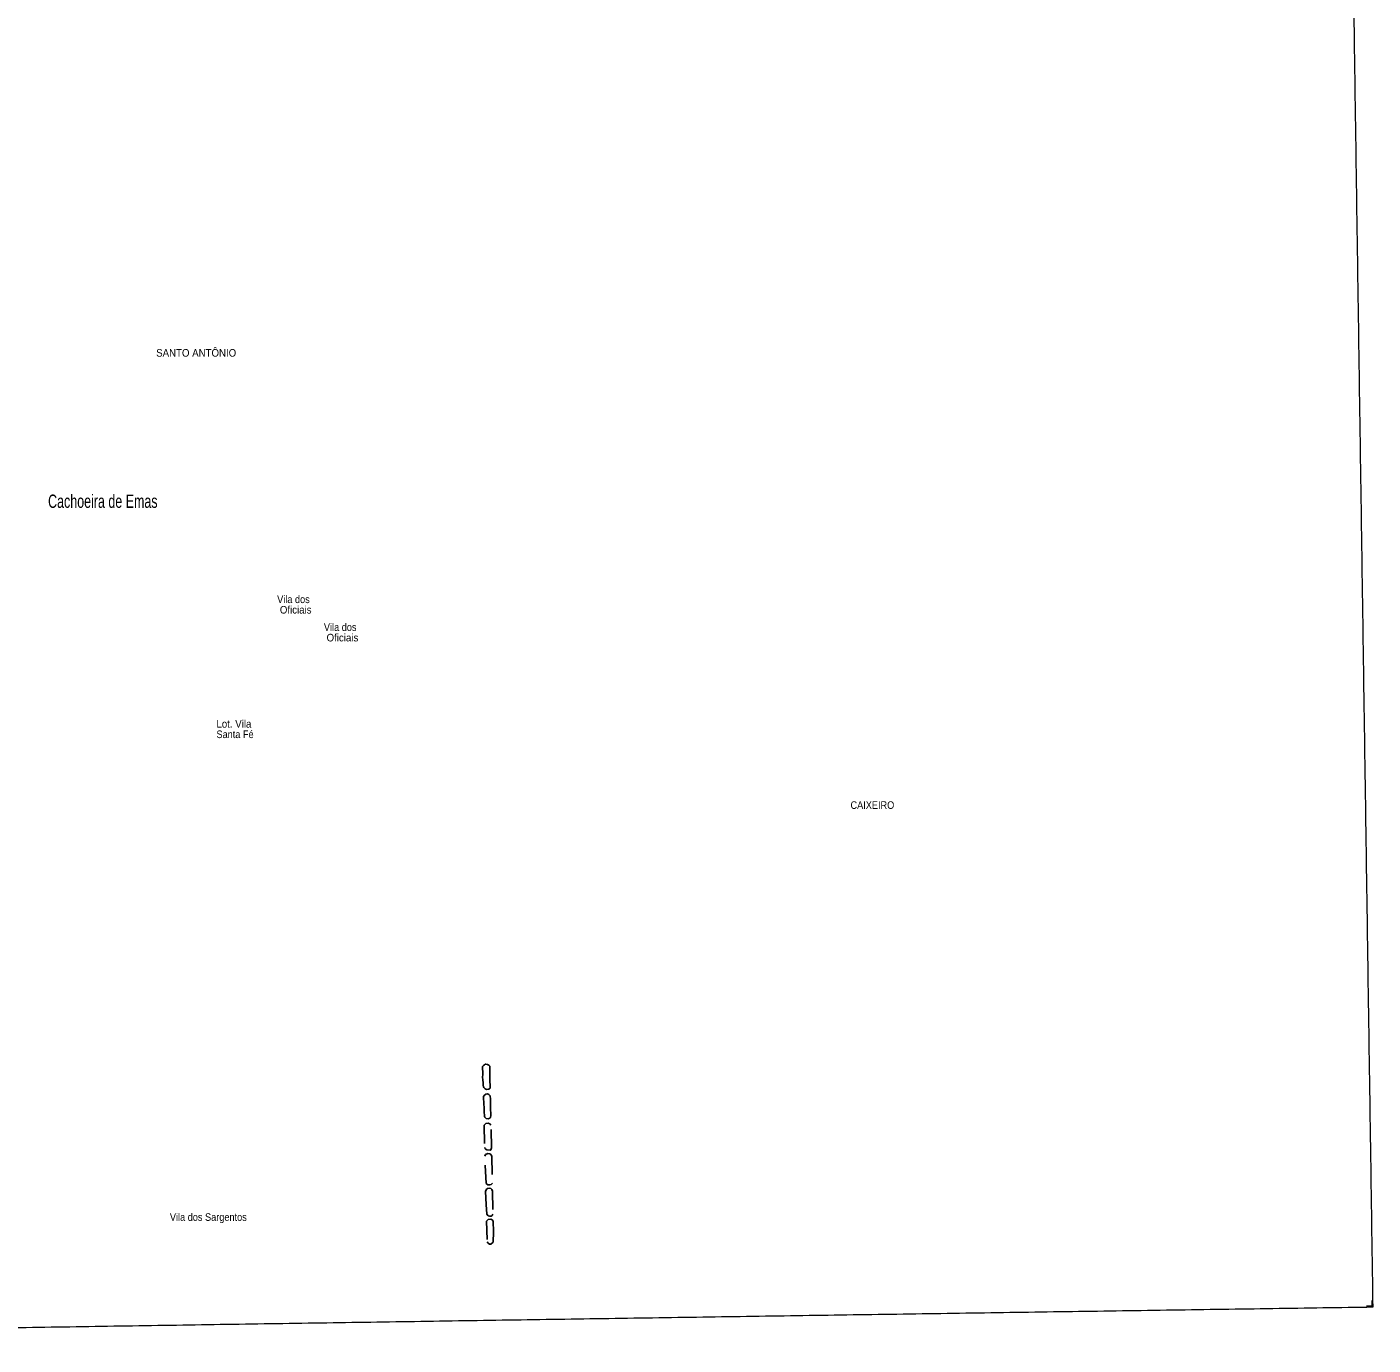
# Model space of a CAD drawing. Extents: x 241.4 to 267.7, y 7565 to 7593.1.
# Drawn here: x 253.55 to 267.7, y 7565.03 to 7578.89 of the extents above; entities that cross this region are included whole.
import ezdxf
from ezdxf.enums import TextEntityAlignment as Align

# ---------------------------------------------------------------- set-up
doc = ezdxf.new("R2010")
doc.units = 0
doc.header["$LTSCALE"] = 0.032
doc.linetypes.add('LONG_DASHED', pattern=[7.5, 6, -1.5])
doc.layers.add('45', color=7, linetype='LONG_DASHED', lineweight=25)
doc.layers.add('63', color=7, linetype='Continuous', lineweight=13)
doc.layers.add('61', color=7, linetype='Continuous')

msp = doc.modelspace()

# ---------------------------------------------------------------- linework, layer by layer
at = {"layer": '45'}
for points in [[(258.3444, 7567.7576), (258.3459, 7567.7522), (258.3479, 7567.7482), (258.3514, 7567.7394), (258.3647, 7567.7247), (258.3801, 7567.72), (258.3979, 7567.7214), (258.4108, 7567.7254), (258.4156, 7567.7321), (258.4161, 7567.7514), (258.4147, 7567.8167), (258.4138, 7567.8809), (258.4134, 7567.8956), (258.4129, 7567.9645), (258.4028, 7567.9755), (258.3877, 7567.9824), (258.3725, 7567.9843), (258.3661, 7567.9838), (258.356, 7567.9797), (258.3473, 7567.9719), (258.3376, 7567.9599), (258.3384, 7567.8786), (258.3386, 7567.8769), (258.337, 7567.8494), (258.3402, 7567.8187), (258.3426, 7567.7879), (258.3426, 7567.766)], [(258.3527, 7567.516), (258.3501, 7567.5775), (258.3474, 7567.6274), (258.3483, 7567.6461), (258.3581, 7567.6595), (258.3714, 7567.6684), (258.3883, 7567.6722), (258.4044, 7567.6651), (258.4177, 7567.6517), (258.4204, 7567.6169), (258.4222, 7567.5276), (258.424, 7567.4464), (258.4222, 7567.4259), (258.4142, 7567.417), (258.3972, 7567.4107), (258.3767, 7567.4134), (258.3624, 7567.4277), (258.3571, 7567.4348), (258.3526, 7567.4902), (258.3525, 7567.4936)], [(258.3542, 7567.3423), (258.3603, 7567.1096), (258.3653, 7567.0962), (258.3809, 7567.0851), (258.4154, 7567.0801), (258.4232, 7567.0851), (258.4304, 7567.1046), (258.4254, 7567.342), (258.4137, 7567.3559), (258.3976, 7567.3637), (258.3725, 7567.3604)], [(258.3751, 7566.7315), (258.3597, 7567.0184), (258.369, 7567.0354), (258.3921, 7567.0462), (258.4122, 7567.0431), (258.4245, 7567.0339), (258.4338, 7567.0184), (258.4399, 7566.7346), (258.4291, 7566.7207), (258.4122, 7566.7145), (258.3937, 7566.7161)], [(258.3685, 7566.6468), (258.3785, 7566.6692), (258.3896, 7566.6785), (258.4058, 7566.6804), (258.425, 7566.6766), (258.4356, 7566.6673), (258.4424, 7566.6487), (258.4449, 7566.4094), (258.4387, 7566.3939), (258.4269, 7566.3877), (258.4089, 7566.3871), (258.3971, 7566.3902), (258.3803, 7566.4082), (258.3735, 7566.5077)], [(258.3799, 7566.3342), (258.3855, 7566.1166), (258.3976, 7566.1027), (258.4115, 7566.0934), (258.4236, 7566.0936), (258.4496, 7566.1132), (258.4515, 7566.2221), (258.4487, 7566.3348), (258.4376, 7566.3497), (258.4227, 7566.3563), (258.3948, 7566.3516)]]:
    msp.add_lwpolyline(points, close=True, dxfattribs=at)
at = {"layer": '63', "lineweight": 25}
msp.add_lwpolyline([(267.63, 7565.4395), (267.6916, 7565.4395), (267.6916, 7565.5002)], dxfattribs=at)
at = {"layer": '63'}
for points in [[(267.7002, 7565.4324), (267.6919, 7565.9974), (267.6836, 7566.5625), (267.6753, 7567.1275), (267.667, 7567.6925), (267.6586, 7568.2576), (267.6503, 7568.8226), (267.642, 7569.3877), (267.6337, 7569.9527), (267.6254, 7570.5178), (267.6171, 7571.0828), (267.6088, 7571.6479), (267.6005, 7572.2129), (267.5922, 7572.778), (267.5839, 7573.343), (267.5757, 7573.9081), (267.5674, 7574.4731), (267.5591, 7575.0382), (267.5508, 7575.6032), (267.5425, 7576.1682), (267.5342, 7576.7333), (267.526, 7577.2983), (267.5177, 7577.8634), (267.5094, 7578.4284), (267.5011, 7578.9935), (267.4929, 7579.5585), (267.4846, 7580.1235), (267.4763, 7580.6886), (267.4681, 7581.2536), (267.4598, 7581.8187), (267.4515, 7582.3837), (267.4433, 7582.9487), (267.435, 7583.5138), (267.4268, 7584.0788), (267.4185, 7584.6439), (267.4102, 7585.2089), (267.402, 7585.7739), (267.3937, 7586.339), (267.3855, 7586.904), (267.3773, 7587.4691), (267.369, 7588.0341), (267.3608, 7588.5991), (267.3525, 7589.1642), (267.3443, 7589.7292), (267.336, 7590.2942), (267.3278, 7590.8593), (267.3196, 7591.4243), (267.3114, 7591.9893), (267.3031, 7592.5544), (267.2949, 7593.1194)], [(241.8778, 7565.0311), (242.4049, 7565.0398), (242.9319, 7565.0484), (243.4589, 7565.0569), (243.9859, 7565.0655), (244.5129, 7565.074), (245.04, 7565.0826), (245.567, 7565.0911), (246.094, 7565.0995), (246.621, 7565.108), (247.148, 7565.1165), (247.675, 7565.1249), (248.202, 7565.1333), (248.729, 7565.1417), (249.256, 7565.1501), (249.783, 7565.1585), (250.31, 7565.1668), (250.837, 7565.1751), (251.364, 7565.1835), (251.891, 7565.1917), (252.418, 7565.2), (252.945, 7565.2083), (253.472, 7565.2165), (253.999, 7565.2247), (254.526, 7565.2329), (255.0529, 7565.2411), (255.5799, 7565.2493), (256.1069, 7565.2575), (256.6339, 7565.2656), (257.1609, 7565.2737), (257.6879, 7565.2818), (258.2148, 7565.2899), (258.7418, 7565.298), (259.2688, 7565.306), (259.7958, 7565.314), (260.3227, 7565.322), (260.8497, 7565.33), (261.3767, 7565.338), (261.9036, 7565.346), (262.4306, 7565.3539), (262.9576, 7565.3618), (263.4845, 7565.3697), (264.0115, 7565.3776), (264.5385, 7565.3855), (265.0654, 7565.3934), (265.5924, 7565.4012), (266.1193, 7565.409), (266.6463, 7565.4168), (267.1732, 7565.4246), (267.7002, 7565.4324)]]:
    msp.add_spline(points, degree=3, dxfattribs=at)

# ---------------------------------------------------------------- texts
at = {"layer": '61'}
for s, width, p in [('SANTO ANTÔNIO', 0.95, (255.3262, 7575.4246)), ('CAIXEIRO', 0.9, (262.4359, 7570.6692))]:
    msp.add_text(s, height=0.08, dxfattribs=dict(at, width=width)).set_placement(p, align=Align.CENTER)
for s, height, width, p in [('Cachoeira de Emas', 0.14, 0.7, (253.7691, 7573.8347)), ('Vila dos', 0.08, 0.9, (256.1775, 7572.8334)), (' Oficiais', 0.08, 0.95, (256.1775, 7572.7234)), ('Vila dos', 0.08, 0.9, (256.6691, 7572.5403)), (' Oficiais', 0.08, 0.95, (256.6691, 7572.4303)), ('Lot. Vila', 0.08, 0.95, (255.5392, 7571.5237)), ('Santa Fé', 0.08, 0.9, (255.5392, 7571.4137)), ('Vila dos Sargentos', 0.08, 0.9, (255.0498, 7566.3373))]:
    msp.add_text(s, height=height, dxfattribs=dict(at, width=width)).set_placement(p)

doc.saveas('drawing.dxf')
